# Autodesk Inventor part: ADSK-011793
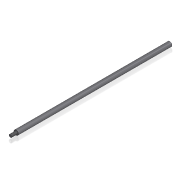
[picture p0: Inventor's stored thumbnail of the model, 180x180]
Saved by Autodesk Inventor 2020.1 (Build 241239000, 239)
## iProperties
Created: 1999-11
Part Number: ADSK-011793
Material: Acier doux
Document SubType Name: Modeling
Designer: kcovelli
Density: 7.86 g/cm^3
Appearance: Metal-Steel(Polish)
Mass: 834.012 g
Surface Area: 271.488 cm^2
Volume: 106.108 cm^3
Control State: 0
Master: False
Checked Out: False
Shininess: 0.0
Length Units: 11269
Angle Units: 11279
Time Units: 11290
Mass Units: 11283
Length Display Precision: 3
Angle Display Precision: 2
Compacted: True
Dimensions: 16x540x16 mm
Mass: 0,834 kg
DocNumber: ADSK-011793.ipt
Folder: 01 - Themengebiete\Simplification\01 - Packaging machine\
VDS_Category: 3D Komponenten
VLT_Material: Acier doux
Density: 0.0
Volumn: 0.0
Area: 0.0
PropertySet Name: Model Information
Author: kcovelli
Revision Number: -
Title: shaft
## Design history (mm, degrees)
node "Solide1"
  node "Extrusion1" dims "d0" = 510, "d1" = 0
  node "Extrusion2" dims "d2" = 10, "d3" = 0
  node "Extrusion3" dims "d5" = 20, "d6" = 0
sketch "Sketch1"
  geometry: C1 r 8 at (0, 0); 1 further point
  constraints: 1 centre point, 1 coincident
  dimensions: "d7" = 16 diameter of C1
sketch "Sketch2"
  geometry: C1 r 8 at (0, 0) reference
sketch "Sketch3"
  geometry: C1 r 8 at (0, 0) reference; C2 r 5 at (0, 0)
  constraints: 1 centre point, 1 coincident
  dimensions: "d4" = 10 diameter of C2
feature "Gewinde1" dims "d8" = 20, "d9" = 0
chamfer "Fase1" distance "d10" = 1; stored, may be unused: second distance "d11" = 2, angle "d12" = 45 deg
node "Corps solides"
node "Corps surfaciques"
